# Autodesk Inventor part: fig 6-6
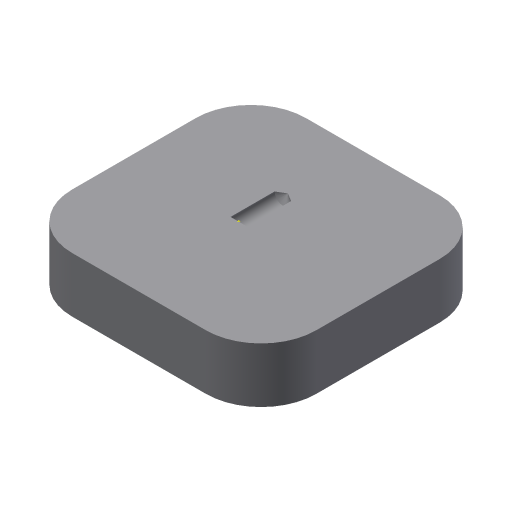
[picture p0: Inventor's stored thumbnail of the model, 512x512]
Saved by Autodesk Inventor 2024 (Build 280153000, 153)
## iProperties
Created: 2004-05
Part Number: fig 6-6
Document SubType Name: Modeling
Designer: CADCIM Technologies
Manufacturer: Standard
Standards Organization: Custom
Density: 1 g/cm^3
Material: Generic
Appearance: Default
Author: CADCIM Technologies
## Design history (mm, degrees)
sketch "Sketch1"
  geometry: L1 (0, 0)-(44.293, 0); L2 (44.293, 0)-(44.293, 42.442); L3 (44.293, 42.442)-(0, 42.442); L4 (0, 42.442)-(0, 0)
  constraints: 8 end point, 2 parallel, 1 horizontal, 1 perpendicular
extrude "Extrusion1" new body sketch "Sketch1" distance "d0" = 10; taper "d1" = 0 deg
fillet "Fillet1" dims "d2" = 10
sketch "Sketch2"
  geometry: 1 further point
sketch "Sketch3"
  geometry: L1 (10, 42.442)-(34.293, 42.442) reference; L2 (0, 10)-(0, 32.442) reference; L3 (34.293, 0)-(10, 0) reference; L4 (44.293, 32.442)-(44.293, 10) reference; A1 r 10 centre (34.293, 32.442) between (44.293, 32.442) and (34.293, 42.442) reference; A2 r 10 centre (10, 32.442) between (10, 42.442) and (0, 32.442) reference; A3 r 10 centre (10, 10) between (0, 10) and (10, 0) reference; A4 r 10 centre (34.293, 10) between (34.293, 0) and (44.293, 10) reference; 1 further point
workpoint "Work Point1"
hole "Hole4" diameter "d33" = 3; stored, may be unused: countersink angle "d37" = 90 deg, drill point angle "d39" = 118 deg; dims "d31" = 10, "d32" = 10, "d34" = 6, "d35" = 4, "d36" = 2, "d38" = 8
body "Solid1"
